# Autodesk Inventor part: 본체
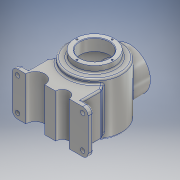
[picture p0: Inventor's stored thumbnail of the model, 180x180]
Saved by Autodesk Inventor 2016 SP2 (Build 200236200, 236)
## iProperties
Created: 2018-08
Part Number: 본체
Material: 알루미늄 6061
Document SubType Name: Modeling
Designer: Administrator
Density: 2.7 g/cm^3
Appearance: 알루미늄 - 평지
Mass: 1940.07 g
Surface Area: 1087.3 cm^2
Volume: 718.546 cm^3
Author: Administrator
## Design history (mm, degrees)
sketch "스케치1"
  geometry: L1 (0, 11.794)-(0, -11.759); L2 (-70, -11.759)-(-70, -1.759); L3 (-70, -1.759)-(-50, -1.759); L4 (-50, 32.882)-(-28.496, 63.592); L5 (-50, -1.759)-(-50, 32.882); L6 (0, 11.794)-(0, 104.496); L7 (-28.496, 63.592)-(0, 63.592); L8 (70, -11.759)-(70, -1.759); L9 (70, -1.759)-(50, -1.759); L10 (50, 32.882)-(28.496, 63.592); L11 (50, -1.759)-(50, 32.882); L12 (28.496, 63.592)-(0, 63.592); L13 (-70, -11.759)-(-45, -11.759); L14 (-10, -11.759)-(0, -11.759); L15 (70, -11.759)-(35, -11.759); L16 (10, -11.759)-(0, -11.759); A1 r 17.5 centre (-27.5, -11.759) between (-10, -11.759) and (-45, -11.759); A2 r 12.5 centre (22.5, -11.759) between (35, -11.759) and (10, -11.759); 1 further point
  constraints: 32 end point, 5 symmetric about line, 4 point on circle, 4 vertical, 2 centre point, 2 horizontal, 2 perpendicular, 2 point on line
  dimensions: "d0" = 20 distance of L2.end L3.end; "d1" = 70 distance of L1.end L2.start; "d2" = 10 distance of L2.start L2.end; "d3" = 35 deg angle of L2 L4; "d4" = 35 diameter of A1; "d5" = 27.5 distance from line of L1 A1.centre; "d81" = 25 diameter of A2
extrude "돌출1" new body sketch "스케치1" stored distance "d6" = 80; taper "d7" = 0 deg
sketch "스케치2"
  geometry: L1 (-11.759, -40)-(-11.759, 40) reference; L2 (-11.759, 40)-(-1.759, 40) reference; L3 (70.241, 57.703)-(70.241, -60); L4 (70.241, 60)-(106.241, 60); L5 (106.241, 60)-(106.241, 48); L6 (106.241, 48)-(120.241, 48); L7 (120.241, 48)-(120.241, -48.671); L8 (32.882, 40)-(63.592, 40) reference; L9 (70.241, 57.703)-(70.241, 60); A1 r 116 centre (70.241, 56) between (70.241, -60) and (120.241, -48.671); 1 further point
  constraints: 12 end point, 3 perpendicular, 2 point on circle, 2 point on line, 2 vertical, 1 centre point, 1 horizontal
  dimensions: "d27" = 82 distance between parallel lines of L1 L3; "d28" = 8 distance between parallel lines of L8 L6; "d29" = 36 distance of L4.start L4.end; "d30" = 12 distance of L4.end L5.end; "d31" = 50 distance between parallel lines of L3 L7; "d33" = 116 radius of A1
revolve "회전1" sketch "스케치2" stored, may be unused: angle "d34" = 90 deg
sketch "스케치3"
  geometry: 1 further point
node "작업 평면2"
sketch "스케치4"
  geometry: L1 (-85, 8)-(15, 8) reference; C1 r 38 at (-35, -42); 1 further point
  constraints: 1 centre point, 1 vertical alignment
  dimensions: "d83" = 76 diameter of C1; "d84" = 50 distance from line of L1 C1.centre
extrude "돌출2" join sketch "스케치4" distance "d38" = 65; taper "d39" = 0 deg
sketch "스케치5"
  geometry: L1 (-71, 20)-(1, 20) reference; L2 (-85, -88.671)-(15, -88.671) reference; L3 (-85, 8)-(15, 8) reference; L4 (-77.398, 0)-(-77.398, -80) reference; L5 (7.398, 0)-(-77.398, 0) reference; L6 (7.398, -80)-(7.398, 0) reference; L7 (-77.398, -80)-(7.398, -80) reference; C1 r 27 at (-35, -42); 2 further points
  constraints: 1 centre point, 1 other
  dimensions: "d85" = 54 diameter of C1; "d87" = 50 distance from line of L3 C1.centre
extrude "돌출3" cut sketch "스케치5" distance "d41" = 65; taper "d42" = 0 deg
sketch "스케치6"
  geometry: L1 (70.241, 60)-(70.241, -50) reference; L2 (34.241, 60)-(106.241, 60) reference; L3 (97.241, 60)-(97.241, 38); L4 (97.241, 38)-(110.241, 38); L5 (110.241, 38)-(110.241, -42.163); L6 (97.241, 60)-(70.241, 60); A1 r 116 centre (70.241, 56) between (20.241, -48.671) and (120.241, -48.671) reference; A2 r 106 centre (70.241, 56) between (70.241, -50) and (110.241, -42.163); 1 further point
  constraints: 10 end point, 3 vertical, 2 perpendicular, 2 point on circle, 1 centre point, 1 horizontal, 1 midpoint, 1 point on line
  dimensions: "d43" = 10 radial gap between concentric circles of A1 A2; "d44" = 27 distance between parallel lines of L1 L3; "d46" = 22 distance of L3.start L3.end
revolve "회전2" sketch "스케치6" stored, may be unused: angle "d47" = 90 deg
sketch "스케치7"
  geometry: 1 further point
chamfer "모따기1" distance "d48" = 1; stored, may be unused: second distance "d49" = 2, angle "d50" = 45 deg
fillet "모깎기1" dims "d51" = 3
chamfer "모따기2" distance "d52" = 1; stored, may be unused: second distance "d53" = 2, angle "d54" = 45 deg
sketch "스케치8"
  geometry: 1 further point
fillet "모깎기2" dims "d55" = 10
sketch "스케치9"
  geometry: C1 r 4 at (-110, 10); C2 r 4 at (-110, 70); C3 r 4 at (10, 70); C4 r 4 at (10, 10); A1 r 10 centre (-110, 10) between (-120, 10) and (-110, 0) reference; A2 r 10 centre (-110, 70) between (-110, 80) and (-120, 70) reference; A3 r 10 centre (10, 70) between (20, 70) and (10, 80) reference; A4 r 10 centre (10, 10) between (10, 0) and (20, 10) reference; 1 further point
  constraints: 4 centre point, 4 coincident
  dimensions: "d56" = 8 diameter of C1; "d57" = 8 diameter of C2; "d58" = 8 diameter of C3
extrude "돌출4" cut sketch "스케치9" distance "d59" = 65; taper "d60" = 0 deg
fillet "모깎기3" dims "d61" = 3
node "작업 평면3"
sketch "스케치10"
  geometry: 2 further points
  constraints: 1 other
sketch "스케치11"
  geometry: C1 r 27 at (0, 0) reference; A1 r 32.5 centre (0, 0) between (0, 32.5) and (32.5, 0); 3 further points
  constraints: 4 point on circle, 1 centre point, 1 coincident
  dimensions: "d63" = 65 diameter of A1
hole "구멍1" sketch "스케치11" at (0, 32.5), (32.5, 0), (0, -32.5), (-32.5, 0) diameter "d64" = 3.242; stored, may be unused: countersink angle "d68" = 90 deg, drill point angle "d70" = 118 deg; dims "d65" = 8, "d66" = 4, "d67" = 2, "d69" = 10
sketch "스케치12"
  geometry: C1 r 27 at (0, 2) reference; A1 r 32.5 centre (0, 2) between (32.5, 2) and (0, -30.5); 2 further points
  constraints: 4 point on circle, 1 centre point, 1 coincident
  dimensions: "d89" = 65 diameter of A1
hole "구멍2" sketch "스케치12" at (32.5, 2), (0, -30.5), (-32.5, 2), (0, 34.5) diameter "d72" = 3.242; stored, may be unused: countersink angle "d76" = 90 deg, drill point angle "d78" = 118 deg; dims "d73" = 8, "d74" = 4, "d75" = 2, "d77" = 10
feature "엠보싱1" dims "d0" = 20, "d1" = 70, "d2" = 10, "d3" = 35 deg, "d4" = 35, "d5" = 27.5, "d27" = 82, "d79" = 0.5, "d80" = 0, "d81" = 25
fillet "모깎기4" dims "d88" = 3
node "솔리드1"
node "투영된 루프1"
other parameters: "d36" = -82, "d62" = 38.75
